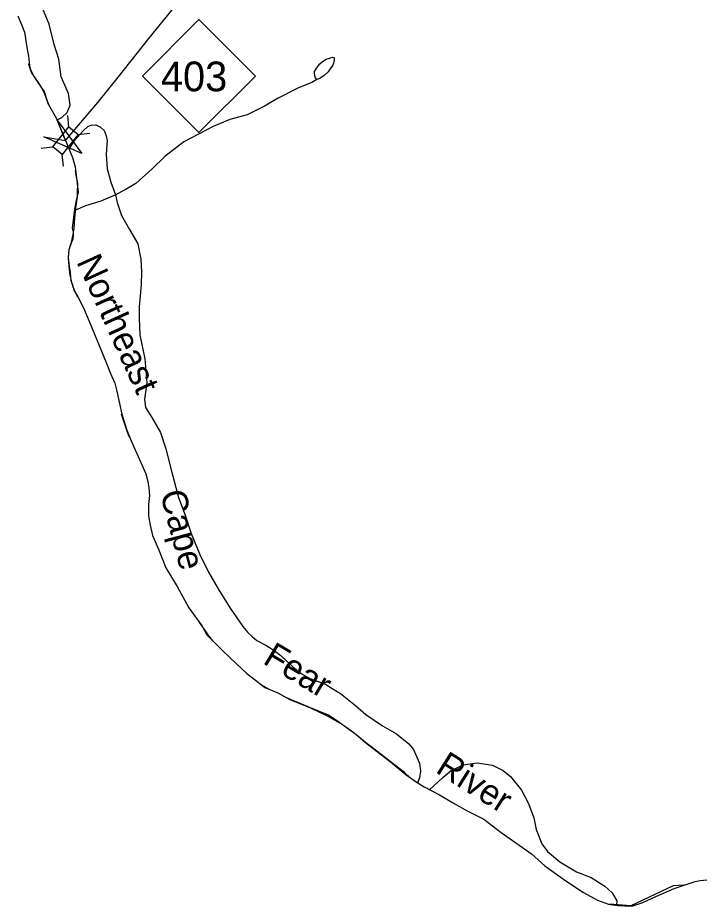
# Model space of a CAD drawing. Extents: x 2206922 to 2357709, y 510027 to 673830.
# Drawn here: x 2304304 to 2308348, y 516900 to 522133 of the extents above; entities that cross this region are included whole.
import ezdxf

# ---------------------------------------------------------------- set-up
doc = ezdxf.new("R2010")
doc.units = 0
for name, color, linetype in [('Exist Boundary Political CountyLine', 7, 'Continuous'), ('Exist Hydrographic Creek Single Shore Label', 7, 'Continuous'), ('Exist Hydrographic Misc Water Feature', 7, 'Continuous'), ('Exist Road Primary NC Attributed', 7, 'Continuous'), ('Exist Road Primary NC Shield CELL', 7, 'Continuous'), ('Exist Road Primary NC Shield Number Label', 7, 'Continuous'), ('Exist Road Primary NC Structure Standard Bridge CELL', 7, 'Continuous'), ('Exist Road Secondary Structure Standard Bridge Attributed CELL', 7, 'Continuous')]:
    doc.layers.add(name, color=color, linetype=linetype)

msp = doc.modelspace()

# ---------------------------------------------------------------- linework, layer by layer
at = {"layer": 'Exist Boundary Political CountyLine'}
for points in [[(2304303.8, 522144.1), (2304326.4, 522094.2), (2304342.9, 522048.5), (2304349.2, 522010.5), (2304357.7, 521958.7), (2304366.4, 521906.8), (2304373, 521852.9), (2304379.1, 521829.1), (2304389.4, 521807.1), (2304401.7, 521781.2), (2304420, 521757.5), (2304440.3, 521725.7), (2304458.6, 521699.9), (2304470.9, 521662.2), (2304485.3, 521622.3), (2304532.2, 521540.8), (2304626.7, 521310), (2304641.3, 521256.1), (2304647.7, 521206.2), (2304654.3, 521156.5), (2304658.7, 521106.4), (2304647.3, 521056.4), (2304638, 521006.2), (2304630.5, 520942.3), (2304625.1, 520894.2), (2304629.4, 520870.2), (2304629.5, 520848.2), (2304627.9, 520828.3), (2304620, 520812.2), (2304604.4, 520766), (2304601.1, 520720), (2304607.5, 520670.1), (2304612, 520632.2), (2304616.5, 520586.2), (2304626.7, 520560.4), (2304635, 520528.5), (2304657.4, 520488.8), (2304690.2, 520425.1), (2304729, 520335.7), (2304825.6, 520102.7), (2304850.2, 520037.1), (2304874.9, 519981.3), (2304887.2, 519933.6), (2304904.1, 519861.7), (2304916.7, 519797.9), (2304945.7, 519704.3), (2304962.3, 519664.6), (2304986.8, 519606.7), (2305013.3, 519549.2), (2305058.4, 519447.6), (2305070.9, 519401.9), (2305075.3, 519361.8), (2305079.8, 519320), (2305074.4, 519266), (2305073.2, 519199.9), (2305083.7, 519144.1), (2305098.3, 519084.3), (2305133.2, 519002.7), (2305176.4, 518893.2), (2305243.4, 518783.9), (2305310.8, 518656.8), (2305389.9, 518549.8), (2305418.6, 518498.1), (2305509.5, 518407.1)], [(2305509.5, 518407.1), (2305592.3, 518328.1), (2305652.8, 518270.7), (2305695.1, 518239.2), (2305759.8, 518187.8), (2305836, 518156.6), (2305906.4, 518117.5), (2306028.8, 518068.8), (2306131.2, 518019.9), (2306217.8, 517971), (2306296.3, 517913.7), (2306362.8, 517856.6), (2306497.9, 517752), (2306590.8, 517675.1), (2306645.2, 517635.7), (2306697.6, 517602.2), (2306787.9, 517555.3), (2306860.4, 517512.2), (2306950.9, 517461), (2307049.3, 517412.2), (2307152.1, 517333.3), (2307331.4, 517209.3), (2307410, 517138.2), (2307533, 517049.6), (2307637.6, 516980.8), (2307720.1, 516935.7), (2307784.4, 516912.3), (2307838.3, 516904.8), (2307922.4, 516899.8), (2307986.1, 516922.6), (2308063.7, 516957.3), (2308171.2, 517004.5), (2308294.6, 517045.8), (2308324.5, 517052.1), (2308364.4, 517054.5)]]:
    msp.add_lwpolyline(points, dxfattribs=at)
at = {"layer": 'Exist Hydrographic Misc Water Feature'}
for points in [[(2304535.4, 521532.8), (2304562.9, 521545.3), (2304594.3, 521575.6), (2304611.9, 521617.7), (2304603.1, 521687.6), (2304560.1, 521785.1), (2304545.1, 521888.9), (2304518, 521976.5), (2304488.9, 522096.2), (2304439.7, 522213.6)], [(2306065.6, 521769.3), (2306057.4, 521779.2), (2306053.5, 521791.2), (2306051.2, 521805.2), (2306053, 521817.2), (2306062.9, 521837.3), (2306082.6, 521861.4), (2306098.4, 521875.6), (2306120.1, 521889.8), (2306134, 521894), (2306146.1, 521898.1), (2306160.1, 521900.3), (2306168.1, 521898.3), (2306168.1, 521892.3), (2306168.1, 521882.4), (2306164.4, 521866.3), (2306160.7, 521854.3), (2306150.7, 521840.2), (2306142.9, 521830.1), (2306132.8, 521814), (2306109.2, 521793.8), (2306083.4, 521775.5), (2306065.6, 521769.3)], [(2304485.4, 521622.3), (2304470.4, 521662), (2304456.4, 521699), (2304452.4, 521709.6), (2304441.6, 521726.6), (2304420.2, 521757.6), (2304416.8, 521762.4), (2304403.7, 521782.7), (2304389, 521801.8), (2304386.4, 521806), (2304378.5, 521828.9), (2304370.6, 521852), (2304369.9, 521861.2)], [(2306065.6, 521769.3), (2306039.7, 521753), (2305954.2, 521718.1), (2305834.9, 521656.9), (2305761.5, 521614.1), (2305655.9, 521561), (2305552.3, 521533.9), (2305454.9, 521492.9), (2305281.8, 521403.1), (2305170.9, 521316), (2305095.7, 521243.2), (2304998.7, 521156.2), (2304937.2, 521119.5), (2304879.3, 521091)], [(2304606.2, 521360.1), (2304638.2, 521410.2), (2304689.7, 521466.7), (2304717.3, 521493), (2304737, 521501.2), (2304763.1, 521503.4), (2304791.2, 521489.7), (2304813.3, 521470), (2304824, 521438.1), (2304830.1, 521410.2), (2304824.8, 521330.2), (2304829.9, 521244.3), (2304852.7, 521164.6), (2304871.3, 521110.9), (2304879.3, 521091)], [(2304644.5, 521000.5), (2304655.6, 521078.6), (2304656.1, 521106.4), (2304656.8, 521156.5), (2304648.3, 521206.3), (2304645.9, 521220.1), (2304644.2, 521233.5)], [(2304879.3, 521091), (2304871.5, 521086.9), (2304793.8, 521052.1), (2304702.4, 521025), (2304644.5, 521000.5)], [(2304879.3, 521091), (2304889.8, 521045.1), (2304914.8, 520969.4), (2304961.6, 520885.9), (2305010.6, 520802.5), (2305029.4, 520710.7), (2305032.3, 520636.8), (2305031.1, 520560.9), (2305018.4, 520430.8), (2305019.2, 520362.8), (2305022.5, 520264.9), (2305051.8, 520123.3), (2305063.5, 519983.5), (2305050.3, 519887.5), (2305056.9, 519837.5), (2305093.4, 519778), (2305144.5, 519690.6), (2305175.4, 519595), (2305208.8, 519463.4), (2305250.5, 519307.9), (2305289.6, 519202.4), (2305324.7, 519094.8), (2305376, 518971.4), (2305427.2, 518868), (2305484.2, 518768.8), (2305555.4, 518655.6), (2305630.4, 518548.4), (2305658.7, 518512.7), (2305685, 518489.1), (2305713.1, 518465.4), (2305765.4, 518438), (2305807.8, 518410.4), (2305854.1, 518376.9), (2305926.9, 518307.7), (2305973.1, 518270.3), (2306025.4, 518240.8), (2306117.8, 518207.9), (2306156.2, 518182.3), (2306204.4, 518152.8), (2306293.2, 518081.8), (2306353.7, 518028.5), (2306452.1, 517961.6), (2306534.7, 517914.5), (2306607.1, 517857.3), (2306635.6, 517823.6), (2306654.3, 517777.8), (2306670.5, 517742.1), (2306677, 517696.1), (2306671.5, 517656.1), (2306658.9, 517626.9)], [(2304657, 520488.6), (2304654, 520495.7), (2304637.6, 520529.5), (2304627.8, 520552.7), (2304625.6, 520560.1), (2304624.2, 520566.7), (2304611, 520626.4), (2304610.2, 520632), (2304606.9, 520670), (2304602.5, 520720.1), (2304601.9, 520726.1), (2304607.3, 520765.5), (2304609.7, 520781.9), (2304619.7, 520812.2), (2304621.4, 520816.7), (2304625, 520828.8), (2304628.7, 520848.3), (2304629.5, 520852.4), (2304632.3, 520869.7), (2304635.9, 520892.4), (2304639.2, 520952.5), (2304644.5, 520994.5), (2304644.5, 521000.5)], [(2304960, 519663.8), (2304946.2, 519704.4), (2304928.3, 519757), (2304914.9, 519797.4)], [(2305453.9, 518462.8), (2305431.1, 518490.3), (2305389.8, 518549.7), (2305386.5, 518554.4), (2305374.2, 518570.9)], [(2305783.2, 518178.2), (2305738.5, 518204.7)], [(2306615.9, 517656.9), (2306583.1, 517687.2), (2306498.4, 517752.6), (2306383.8, 517841.1), (2306363.3, 517857.2), (2306294.9, 517912), (2306270.5, 517931.5), (2306216.4, 517969), (2306194.5, 517984.1), (2306133.6, 518026.1), (2306028.8, 518068.8), (2306015, 518074.5), (2305910.9, 518117.6), (2305907.1, 518119.2), (2305892.6, 518125.1)], [(2306729.6, 517585.5), (2306807.4, 517657.6), (2306856.9, 517700.1), (2306928.4, 517732.8), (2307010.2, 517743.7), (2307100.5, 517730.7), (2307164.6, 517699.4), (2307206.9, 517663.8), (2307271.9, 517582.6), (2307312.7, 517505.1), (2307343.6, 517419.5), (2307358.2, 517351.6), (2307391.2, 517268.1), (2307425.7, 517222.5), (2307498.3, 517161.2), (2307595, 517102.3), (2307681.2, 517069.3), (2307761.7, 517018.2), (2307806, 516978.6), (2307832.5, 516931), (2307831.7, 516905.7)], [(2308228.1, 517023.5), (2308165.5, 517019.7), (2307916.4, 516901.4), (2307790.6, 516911.4)]]:
    msp.add_lwpolyline(points, dxfattribs=at)
at = {"layer": 'Exist Road Primary NC Attributed'}
msp.add_lwpolyline([(2304585.6, 521410.4), (2304774.8, 521635), (2304896.7, 521784.7), (2305075.9, 522012), (2305249.6, 522222.8), (2305364.1, 522370.6), (2305590.4, 522698.7), (2305871.2, 523129.4), (2306352.4, 523854.9), (2306594, 524231.5)], dxfattribs=at)
at = {"layer": 'Exist Road Primary NC Shield CELL'}
msp.add_lwpolyline([(2305038.2, 521790), (2305371.2, 522123), (2305704.2, 521790), (2305371.2, 521457)], close=True, dxfattribs=at)
at = {"layer": 'Exist Road Primary NC Structure Standard Bridge CELL'}
for p, q in [((2304605.2, 521489.8), (2304597.8, 521558.4)), ((2304658.9, 521446.5), (2304727.5, 521453.9)), ((2304441.6, 521364.9), (2304510.2, 521372.3)), ((2304572.6, 521259.5), (2304565.2, 521328))]:
    msp.add_line(p, q, dxfattribs=at)
msp.add_lwpolyline([(2304510.2, 521372.3), (2304604.9, 521490), (2304659.9, 521445.7), (2304565.2, 521328)], close=True, dxfattribs=at)
at = {"layer": 'Exist Road Secondary Structure Standard Bridge Attributed CELL'}
msp.add_lwpolyline([(2304536, 521530.6), (2304680.9, 521334.5), (2304457.4, 521431.8), (2304585.6, 521410.4)], close=True, dxfattribs=at)

# ---------------------------------------------------------------- texts
at = {"layer": 'Exist Hydrographic Creek Single Shore Label'}
for s, rotation, p in [('Northeast', 294.5006, (2304647.3, 520696.7)), ('Cape', 284.7509, (2305141.4, 519332.3)), ('Fear', 329.0795, (2305741.3, 518333.5)), ('River', 327.82, (2306758.8, 517691.8))]:
    msp.add_text(s, height=150, rotation=rotation, dxfattribs=at).set_placement(p)
at = {"layer": 'Exist Road Primary NC Shield Number Label'}
msp.add_text('403', height=175, dxfattribs=at).set_placement((2305147.3, 521700.3))

doc.saveas('drawing.dxf')
